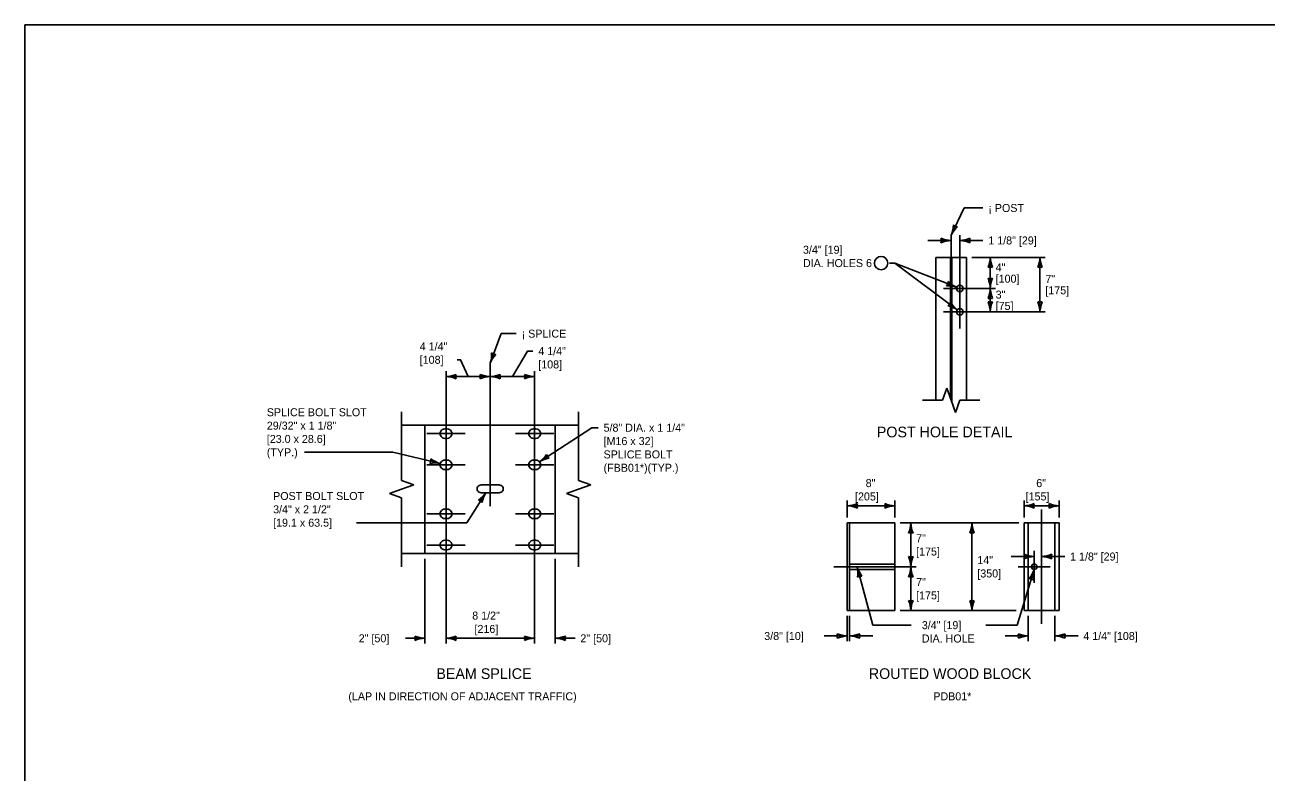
# Model space of a CAD drawing. Extents: x 49991.4 to 50021, y 49987.6 to 50011.4.
# Drawn here: x 49999.38 to 50008.69, y 49993.4 to 49999 of the extents above; entities that cross this region are included whole.
import ezdxf

# ---------------------------------------------------------------- set-up
doc = ezdxf.new("R2010")
doc.units = 0
for name, color, linetype in [('Level 1', 7, 'Continuous'), ('Level 2', 7, 'Continuous'), ('Level 3', 7, 'Continuous'), ('Level 4', 7, 'Continuous'), ('Level 5', 7, 'Continuous'), ('Level 6', 7, 'Continuous')]:
    doc.layers.add(name, color=color, linetype=linetype)

msp = doc.modelspace()

# ---------------------------------------------------------------- linework, layer by layer
at = {"layer": 'Level 1'}
for p, q in [((50006.2125, 49997.2566), (50006.4424, 49997.2566)), ((50006.2125, 49997.2566), (50006.2125, 49996.1857)), ((50006.4424, 49997.2566), (50006.4424, 49996.1857)), ((50002.2084, 49995.9992), (50003.5354, 49995.9992)), ((50002.3835, 49995.0378), (50002.3835, 49995.9992)), ((50002.5326, 49995.9712), (50002.5496, 49995.9712)), ((50003.197, 49995.9712), (50003.214, 49995.9712)), ((50002.5326, 49995.9005), (50002.5496, 49995.9005)), ((50003.197, 49995.9005), (50003.214, 49995.9005)), ((50002.5326, 49995.7373), (50002.5496, 49995.7373)), ((50003.197, 49995.7373), (50003.214, 49995.7373)), ((50002.5326, 49995.6666), (50002.5496, 49995.6666)), ((50003.197, 49995.6666), (50003.214, 49995.6666)), ((50002.9404, 49995.5512), (50002.8037, 49995.5512)), ((50002.8037, 49995.4926), (50002.9404, 49995.4926)), ((50002.5326, 49995.3705), (50002.5496, 49995.3705)), ((50003.197, 49995.3705), (50003.214, 49995.3705)), ((50002.5326, 49995.2997), (50002.5496, 49995.2997)), ((50003.197, 49995.2997), (50003.214, 49995.2997)), ((50005.5486, 49995.2663), (50005.9062, 49995.2663)), ((50005.5486, 49995.2663), (50005.5486, 49994.6097)), ((50005.9062, 49995.2663), (50005.9062, 49994.6097)), ((50006.8742, 49995.2663), (50006.8742, 49994.6097)), ((50006.8742, 49995.2663), (50007.1381, 49995.2663)), ((50006.9065, 49995.2663), (50006.9065, 49994.6097)), ((50007.1058, 49995.2663), (50007.1058, 49994.6097)), ((50007.1381, 49995.2663), (50007.1381, 49994.6097)), ((50002.5326, 49995.1364), (50002.5496, 49995.1364)), ((50003.197, 49995.1364), (50003.214, 49995.1364)), ((50002.2084, 49995.0378), (50003.5354, 49995.0378)), ((50002.5326, 49995.0657), (50002.5496, 49995.0657)), ((50003.197, 49995.0657), (50003.214, 49995.0657)), ((50005.5486, 49994.6097), (50005.9062, 49994.6097)), ((50006.8742, 49994.6097), (50007.1381, 49994.6097))]:
    msp.add_line(p, q, dxfattribs=at)
msp.add_lwpolyline([(49999.3835, 49998.9992), (50016.7501, 49998.9992), (50016.7501, 49987.7988), (49999.3835, 49987.7988)], close=True, dxfattribs=at)
for centre, radius in [((50006.3931, 49997.0236), 0.0237), ((50006.3931, 49996.8482), 0.0237), ((50006.9505, 49994.938), 0.0205)]:
    msp.add_circle(centre, radius, dxfattribs=at)
for centre, major_axis, ratio, start_param, end_param in [((50002.5326, 49995.9359), (-0.0354, 0), 0.998676, 4.712389, 7.853982), ((50002.5496, 49995.9359), (-0.0354, 0), 0.998676, 1.570796, 4.712389), ((50003.197, 49995.9359), (-0.0354, 0), 0.998676, 4.712389, 7.853982), ((50003.214, 49995.9359), (-0.0354, 0), 0.998676, 1.570796, 4.712389), ((50002.5326, 49995.702), (-0.0354, 0), 0.998676, 4.712389, 7.853982), ((50002.5496, 49995.702), (-0.0354, 0), 0.998676, 1.570796, 4.712389), ((50003.197, 49995.702), (-0.0354, 0), 0.998676, 4.712389, 7.853982), ((50003.214, 49995.702), (-0.0354, 0), 0.998676, 1.570796, 4.712389), ((50002.8037, 49995.5219), (-0.0294, 0), 0.995211, 4.712389, 7.853982), ((50002.9404, 49995.5219), (-0.0296, 0), 0.988923, 1.570796, 4.712389), ((50002.5326, 49995.3351), (-0.0354, 0), 0.998676, 4.712389, 7.853982), ((50002.5496, 49995.3351), (-0.0354, 0), 0.998676, 1.570796, 4.712389), ((50003.197, 49995.3351), (-0.0354, 0), 0.998676, 4.712389, 7.853982), ((50003.214, 49995.3351), (-0.0354, 0), 0.998676, 1.570796, 4.712389), ((50002.5326, 49995.1011), (-0.0354, 0), 0.998676, 4.712389, 7.853982), ((50002.5496, 49995.1011), (-0.0354, 0), 0.998676, 1.570796, 4.712389), ((50003.197, 49995.1011), (-0.0354, 0), 0.998676, 4.712389, 7.853982), ((50003.214, 49995.1011), (-0.0354, 0), 0.998676, 1.570796, 4.712389)]:
    msp.add_ellipse(centre, major_axis=major_axis, ratio=ratio, start_param=start_param, end_param=end_param, dxfattribs=at)
at = {"layer": 'Level 2'}
msp.add_circle((50005.8029, 49997.2139), 0.05, dxfattribs=at)
at = {"layer": 'Level 3'}
for p, q in [((50006.3275, 49997.4235), (50006.4252, 49997.6268)), ((50006.4252, 49997.6268), (50006.5665, 49997.6268)), ((50006.3275, 49997.3835), (50006.154, 49997.3835)), ((50006.3931, 49997.3835), (50006.5665, 49997.3835)), ((50005.8667, 49997.2139), (50005.9067, 49997.2139)), ((50005.9067, 49997.2139), (50006.3741, 49996.8625)), ((50005.9067, 49997.2139), (50006.371, 49997.0322)), ((50006.4824, 49997.2566), (50007.034, 49997.2566)), ((50006.6216, 49997.0236), (50006.6216, 49997.2566)), ((50006.994, 49997.2566), (50006.994, 49996.8482)), ((50006.6216, 49996.8482), (50006.6216, 49997.0236)), ((50002.8721, 49996.4632), (50002.955, 49996.6852)), ((50002.955, 49996.6852), (50003.0681, 49996.6852)), ((50002.5411, 49996.3632), (50002.8721, 49996.3632)), ((50003.2055, 49996.3632), (50002.8721, 49996.3632)), ((50003.6342, 49995.9802), (50003.2409, 49995.7249)), ((50003.6822, 49995.9802), (50003.6342, 49995.9802)), ((50002.1431, 49995.796), (50001.4813, 49995.796)), ((50002.4986, 49995.712), (50002.1431, 49995.796)), ((50002.6959, 49995.2684), (50002.8394, 49995.4926)), ((50005.5486, 49995.3063), (50005.5486, 49995.4352)), ((50005.9062, 49995.3952), (50005.5486, 49995.3952)), ((50005.9063, 49995.4352), (50005.9062, 49995.3063)), ((50006.8742, 49995.3063), (50006.8742, 49995.4352)), ((50007.1381, 49995.3952), (50006.8742, 49995.3952)), ((50007.1381, 49995.3063), (50007.1381, 49995.4352)), ((50001.8709, 49995.2684), (50002.6959, 49995.2684)), ((50005.9462, 49995.2663), (50006.8342, 49995.2663)), ((50006.0253, 49994.938), (50006.0253, 49995.2663)), ((50006.4842, 49995.2663), (50006.4842, 49994.6097)), ((50002.3835, 49994.9978), (50002.3835, 49994.3622)), ((50003.3603, 49994.9978), (50003.3603, 49994.3622)), ((50006.7771, 49995.0148), (50006.9505, 49995.0148)), ((50007.0062, 49995.0148), (50007.1796, 49995.0148)), ((50005.7398, 49994.5006), (50005.6225, 49994.938)), ((50006.0253, 49994.938), (50006.0253, 49994.6097)), ((50006.9505, 49994.9175), (50006.823, 49994.5006)), ((50005.9462, 49994.6097), (50006.8144, 49994.6097)), ((50005.5486, 49994.5697), (50005.5486, 49994.3794)), ((50005.5662, 49994.5697), (50005.5662, 49994.3794)), ((50006.9065, 49994.3794), (50006.9065, 49994.5697)), ((50007.1058, 49994.5697), (50007.1058, 49994.3794)), ((50005.5486, 49994.4194), (50005.3752, 49994.4194)), ((50005.7396, 49994.4194), (50005.5662, 49994.4194)), ((50005.7398, 49994.5006), (50006.0281, 49994.5006)), ((50006.5877, 49994.5006), (50006.823, 49994.5006)), ((50006.9065, 49994.4194), (50006.7331, 49994.4194)), ((50007.1058, 49994.4194), (50007.2792, 49994.4194)), ((50002.2377, 49994.4022), (50002.3835, 49994.4022)), ((50002.5411, 49994.4022), (50003.2055, 49994.4022)), ((50003.5085, 49994.4022), (50003.3603, 49994.4022))]:
    msp.add_line(p, q, dxfattribs=at)
for points in [[(50002.7066, 49996.3632), (50002.6505, 49996.4892), (50002.6245, 49996.4892)], [(50003.0388, 49996.3632), (50003.1529, 49996.5544), (50003.1927, 49996.5544)]]:
    msp.add_lwpolyline(points, dxfattribs=at)
for centre, radius, start, end in [((50006.1128, 49997.5141), 0.233, 337.12584, 356.37569), ((50006.3831, 49997.5391), 0.0548, 226.43734, 262.15971), ((50006.3366, 49997.6057), 0.2223, 247.45601, 267.63952), ((50006.1992, 49997.3835), 0.0548, 342.13882, 17.86118), ((50006.5236, 49997.3189), 0.2223, 131.75454, 151.93804), ((50006.3816, 49997.6162), 0.233, 272.82731, 292.07716), ((50006.5213, 49997.3835), 0.0548, 162.13882, 197.86118), ((50006.3389, 49997.1508), 0.233, 92.82731, 112.07716), ((50006.3839, 49997.1614), 0.2223, 67.45601, 87.63952), ((50006.3994, 49997.2657), 0.2223, 337.45601, 357.63952), ((50006.8543, 49997.2681), 0.233, 182.82731, 202.07716), ((50006.7719, 49997.2657), 0.2223, 337.45601, 357.63952), ((50007.2267, 49997.2681), 0.233, 182.82731, 202.07716), ((50006.6216, 49997.1284), 0.0548, 72.13882, 107.86118), ((50006.994, 49997.1284), 0.0548, 72.13882, 107.86118), ((50006.2516, 49997.0789), 0.0548, 320.76761, 356.48997), ((50006.2969, 49996.8113), 0.233, 71.4561, 90.70595), ((50006.4605, 49997.2357), 0.2223, 226.0848, 246.26831), ((50006.6216, 49997.1518), 0.0548, 252.13882, 287.86118), ((50006.3889, 49997.0121), 0.233, 2.82731, 22.07716), ((50006.3994, 49997.0327), 0.2223, 337.45601, 357.63952), ((50006.8437, 49997.0144), 0.2223, 157.45601, 177.63952), ((50006.8543, 49997.0351), 0.233, 182.82731, 202.07716), ((50006.6216, 49996.8954), 0.0548, 72.13882, 107.86118), ((50006.2716, 49996.9395), 0.0548, 305.20124, 340.9236), ((50006.2435, 49996.6696), 0.233, 55.88973, 75.13958), ((50006.5149, 49997.0345), 0.2223, 210.51843, 230.70194), ((50006.6216, 49996.9765), 0.0548, 252.13882, 287.86118), ((50006.3889, 49996.8367), 0.233, 2.82731, 22.07716), ((50006.8437, 49996.8391), 0.2223, 157.45601, 177.63952), ((50006.994, 49996.9765), 0.0548, 252.13882, 287.86118), ((50006.7613, 49996.8367), 0.233, 2.82731, 22.07716), ((50007.2161, 49996.8391), 0.2223, 157.45601, 177.63952), ((50002.6501, 49996.5339), 0.233, 342.34834, 1.59819), ((50003.077, 49996.3769), 0.2223, 136.97704, 157.16055), ((50002.917, 49996.5833), 0.0548, 231.65985, 267.38221), ((50002.5296, 49996.5959), 0.233, 272.82731, 292.07716), ((50002.6693, 49996.3632), 0.0548, 162.13882, 197.86118), ((50002.8813, 49996.5853), 0.2223, 247.45601, 267.63952), ((50002.7439, 49996.3632), 0.0548, 342.13882, 17.86118), ((50002.8606, 49996.5959), 0.233, 272.82731, 292.07716), ((50003.0003, 49996.3632), 0.0548, 162.13882, 197.86118), ((50003.2147, 49996.5853), 0.2223, 247.45601, 267.63952), ((50003.0773, 49996.3632), 0.0548, 342.13882, 17.86118), ((50002.5319, 49996.1411), 0.2223, 67.45601, 87.63952), ((50002.8836, 49996.1305), 0.233, 92.82731, 112.07716), ((50002.8629, 49996.1411), 0.2223, 67.45601, 87.63952), ((50003.217, 49996.1305), 0.233, 92.82731, 112.07716), ((50002.3738, 49995.7415), 0.0548, 328.85016, 4.57253), ((50002.5586, 49995.9261), 0.2223, 234.16736, 254.35086), ((50003.1043, 49995.9136), 0.233, 305.92164, 325.17149), ((50003.3546, 49995.5338), 0.2223, 100.55034, 120.73384), ((50003.3484, 49995.7949), 0.0548, 195.23314, 230.95551), ((50002.4563, 49995.4829), 0.233, 79.53866, 98.78851), ((50002.6573, 49995.6201), 0.2223, 304.8248, 325.00831), ((50003.0416, 49995.3768), 0.233, 150.1961, 169.44595), ((50002.7703, 49995.3846), 0.0548, 39.50761, 75.22997), ((50005.5371, 49995.628), 0.233, 272.82731, 292.07716), ((50005.5395, 49995.1731), 0.2223, 67.45601, 87.63952), ((50005.6768, 49995.3952), 0.0548, 162.13882, 197.86118), ((50005.9154, 49995.6174), 0.2223, 247.45601, 267.63952), ((50005.778, 49995.3952), 0.0548, 342.13882, 17.86118), ((50005.9177, 49995.1625), 0.233, 92.82731, 112.07716), ((50006.8628, 49995.628), 0.233, 272.82731, 292.07716), ((50006.8651, 49995.1731), 0.2223, 67.45601, 87.63952), ((50007.0025, 49995.3952), 0.0548, 162.13882, 197.86118), ((50007.1472, 49995.6174), 0.2223, 247.45601, 267.63952), ((50007.0098, 49995.3952), 0.0548, 342.13882, 17.86118), ((50007.1496, 49995.1625), 0.233, 92.82731, 112.07716), ((50005.8032, 49995.2755), 0.2223, 337.45601, 357.63952), ((50006.258, 49995.2778), 0.233, 182.82731, 202.07716), ((50006.2621, 49995.2755), 0.2223, 337.45601, 357.63952), ((50006.717, 49995.2778), 0.233, 182.82731, 202.07716), ((50006.0253, 49995.1381), 0.0548, 72.13882, 107.86118), ((50006.4842, 49995.1381), 0.0548, 72.13882, 107.86118), ((50006.0253, 49995.0662), 0.0548, 252.13882, 287.86118), ((50005.7926, 49994.9265), 0.233, 2.82731, 22.07716), ((50006.2474, 49994.9288), 0.2223, 157.45601, 177.63952), ((50006.9596, 49995.2369), 0.2223, 247.45601, 267.63952), ((50006.8222, 49995.0148), 0.0548, 342.13882, 17.86118), ((50006.962, 49994.7821), 0.233, 92.82731, 112.07716), ((50006.9947, 49995.2475), 0.233, 272.82731, 292.07716), ((50006.997, 49994.7927), 0.2223, 67.45601, 87.63952), ((50007.1344, 49995.0148), 0.0548, 162.13882, 197.86118), ((50005.4056, 49994.8893), 0.2223, 352.45601, 12.63952), ((50005.8444, 49995.0093), 0.233, 197.82731, 217.07716), ((50005.8032, 49994.9471), 0.2223, 337.45601, 357.63952), ((50006.258, 49994.9495), 0.233, 182.82731, 202.07716), ((50006.7395, 49994.9877), 0.2223, 321.4053, 341.58881), ((50007.1773, 49994.8642), 0.233, 166.7766, 186.02645), ((50005.6557, 49994.8141), 0.0548, 87.13882, 122.86118), ((50006.0253, 49994.8098), 0.0548, 72.13882, 107.86118), ((50006.915, 49994.7943), 0.0548, 56.08811, 91.81047), ((50006.0253, 49994.7379), 0.0548, 252.13882, 287.86118), ((50005.7926, 49994.5982), 0.233, 2.82731, 22.07716), ((50006.2474, 49994.6005), 0.2223, 157.45601, 177.63952), ((50006.4842, 49994.7379), 0.0548, 252.13882, 287.86118), ((50006.2515, 49994.5982), 0.233, 2.82731, 22.07716), ((50006.7064, 49994.6005), 0.2223, 157.45601, 177.63952), ((50002.3927, 49994.6243), 0.2223, 247.45601, 267.63952), ((50002.2553, 49994.4022), 0.0548, 342.13882, 17.86118), ((50002.5296, 49994.6349), 0.233, 272.82731, 292.07716), ((50002.6693, 49994.4022), 0.0548, 162.13882, 197.86118), ((50003.2147, 49994.6243), 0.2223, 247.45601, 267.63952), ((50003.0773, 49994.4022), 0.0548, 342.13882, 17.86118), ((50003.3488, 49994.6349), 0.233, 272.82731, 292.07716), ((50003.4885, 49994.4022), 0.0548, 162.13882, 197.86118), ((50005.5578, 49994.6415), 0.2223, 247.45601, 267.63952), ((50005.4204, 49994.4194), 0.0548, 342.13882, 17.86118), ((50005.5601, 49994.1867), 0.233, 92.82731, 112.07716), ((50005.5547, 49994.6521), 0.233, 272.82731, 292.07716), ((50005.557, 49994.1973), 0.2223, 67.45601, 87.63952), ((50005.6944, 49994.4194), 0.0548, 162.13882, 197.86118), ((50006.9156, 49994.6415), 0.2223, 247.45601, 267.63952), ((50006.7783, 49994.4194), 0.0548, 342.13882, 17.86118), ((50006.918, 49994.1867), 0.233, 92.82731, 112.07716), ((50007.0943, 49994.6521), 0.233, 272.82731, 292.07716), ((50007.0967, 49994.1973), 0.2223, 67.45601, 87.63952), ((50007.234, 49994.4194), 0.0548, 162.13882, 197.86118), ((50002.395, 49994.1695), 0.233, 92.82731, 112.07716), ((50002.5319, 49994.1801), 0.2223, 67.45601, 87.63952), ((50003.217, 49994.1695), 0.233, 92.82731, 112.07716), ((50003.3511, 49994.1801), 0.2223, 67.45601, 87.63952)]:
    msp.add_arc(centre, radius, start, end, dxfattribs=at)
at = {"layer": 'Level 4'}
for p, q in [((50006.322, 49997.2566), (50006.322, 49996.201)), ((50006.3329, 49997.2566), (50006.3329, 49996.1701)), ((50003.3603, 49995.0378), (50003.3603, 49995.9992)), ((50005.5662, 49995.2663), (50005.5662, 49994.6097)), ((50005.5662, 49994.9585), (50005.9062, 49994.9585)), ((50005.5662, 49994.9175), (50005.9062, 49994.9175))]:
    msp.add_line(p, q, dxfattribs=at)
at = {"layer": 'Level 5'}
for p, q in [((50006.3275, 49997.2566), (50006.3275, 49997.4235)), ((50006.3931, 49997.4235), (50006.3931, 49996.7245)), ((50006.2694, 49997.0236), (50006.6616, 49997.0236)), ((50006.2694, 49996.8482), (50007.034, 49996.8482)), ((50002.5411, 49994.3622), (50002.5411, 49996.4032)), ((50002.8721, 49995.3926), (50002.8721, 49996.4632)), ((50003.2055, 49994.3622), (50003.2055, 49996.4032)), ((50002.6851, 49995.9359), (50002.3971, 49995.9359)), ((50003.3495, 49995.9359), (50003.0615, 49995.9359)), ((50002.6851, 49995.702), (50002.3971, 49995.702)), ((50003.3495, 49995.702), (50003.0615, 49995.702)), ((50007.0062, 49995.3663), (50007.0062, 49994.5097)), ((50002.6851, 49995.3351), (50002.3971, 49995.3351)), ((50003.3495, 49995.3351), (50003.0615, 49995.3351)), ((50002.6851, 49995.1011), (50002.3971, 49995.1011)), ((50003.3495, 49995.1011), (50003.0615, 49995.1011)), ((50006.9505, 49994.8175), (50006.9505, 49995.0585)), ((50005.4486, 49994.938), (50006.0653, 49994.938)), ((50006.8299, 49994.938), (50007.071, 49994.938))]:
    msp.add_line(p, q, dxfattribs=at)
at = {"layer": 'Level 6'}
for p, q in [((50006.1125, 49996.1857), (50006.2626, 49996.1857)), ((50006.2626, 49996.1857), (50006.295, 49996.2771)), ((50006.3274, 49996.1857), (50006.295, 49996.2771)), ((50006.3598, 49996.0943), (50006.3274, 49996.1857)), ((50006.3598, 49996.0943), (50006.3922, 49996.1857)), ((50006.3922, 49996.1857), (50006.5424, 49996.1857)), ((50002.2084, 49996.0992), (50002.2084, 49995.5834)), ((50003.5354, 49996.0992), (50003.5354, 49995.5834)), ((50002.2998, 49995.551), (50002.2084, 49995.5834)), ((50002.2998, 49995.551), (50002.2084, 49995.5186)), ((50003.6268, 49995.551), (50003.5354, 49995.5834)), ((50003.6268, 49995.551), (50003.5354, 49995.5186)), ((50002.2084, 49995.5186), (50002.117, 49995.4862)), ((50002.2084, 49995.4538), (50002.117, 49995.4862)), ((50002.2084, 49995.4538), (50002.2084, 49994.9378)), ((50003.5354, 49995.5186), (50003.444, 49995.4862)), ((50003.5354, 49995.4538), (50003.444, 49995.4862)), ((50003.5354, 49995.4538), (50003.5354, 49994.9378))]:
    msp.add_line(p, q, dxfattribs=at)

# ---------------------------------------------------------------- texts
at = {"layer": 'Level 2'}
for s, height, p in [('¡ POST', 0.06, (50006.6065, 49997.5968)), ('1 1/8" [29]', 0.06, (50006.6065, 49997.3535)), ('4"', 0.06, (50006.6616, 49997.152)), ('[100]', 0.06, (50006.6616, 49997.067)), ('7"', 0.06, (50007.034, 49997.0649)), ('[175]', 0.06, (50007.034, 49996.9799)), ('3"', 0.06, (50006.6616, 49996.9478)), ('[75]', 0.06, (50006.6616, 49996.8628)), ('¡ SPLICE', 0.06, (50003.1081, 49996.6552)), ('4 1/4"', 0.06, (50003.2327, 49996.5244)), ('[108]', 0.06, (50003.2327, 49996.4244)), ('5/8" DIA. x 1 1/4"', 0.06, (50003.7222, 49995.9502)), ('[M16 x 32]', 0.06, (50003.7222, 49995.8502)), ('POST HOLE DETAIL', 0.08, (50005.7707, 49995.9082)), ('SPLICE BOLT ', 0.06, (50003.7222, 49995.7502)), ('(FBB01*)(TYP.) ', 0.06, (50003.7222, 49995.6502)), ('8"', 0.06, (50005.6871, 49995.5352)), ('6"', 0.06, (50006.9658, 49995.5352)), ('[205]', 0.06, (50005.6072, 49995.4352)), ('[155]', 0.06, (50006.8859, 49995.4352)), ('7"', 0.06, (50006.0653, 49995.1224)), ('[175]', 0.06, (50006.0653, 49995.0224)), ('14"', 0.06, (50006.5242, 49994.958)), ('1 1/8" [29]', 0.06, (50007.2196, 49994.9848)), ('[350]', 0.06, (50006.5242, 49994.858)), ('7"', 0.06, (50006.0653, 49994.7938)), ('[175]', 0.06, (50006.0653, 49994.6938)), ('8 1/2"', 0.06, (50002.7376, 49994.5422)), ('2" [50]', 0.06, (50001.8866, 49994.3722)), ('[216]', 0.06, (50002.7545, 49994.4422)), ('2" [50]', 0.06, (50003.5485, 49994.3722)), ('3/8" [10]', 0.06, (50004.9266, 49994.3894)), ('4 1/4" [108]', 0.06, (50007.3192, 49994.3894)), ('BEAM SPLICE', 0.08, (50002.4688, 49994.0974)), ('ROUTED WOOD BLOCK', 0.08, (50005.7107, 49994.0974)), ('(LAP IN DIRECTION OF ADJACENT TRAFFIC)', 0.06, (50001.8089, 49993.9374)), ('PDB01*', 0.06, (50006.1941, 49993.9374))]:
    msp.add_text(s, height=height, dxfattribs=at).set_placement(p)
for s, p in [('3/4" [19]', (50005.2171, 49997.2839)), ('DIA. HOLES 6', (50005.2171, 49997.1839)), ('4 1/4"', (50002.344, 49996.5592)), ('[108]', (50002.344, 49996.4592)), ('SPLICE BOLT SLOT', (50001.1976, 49996.066)), ('29/32" x 1 1/8"', (50001.1976, 49995.966)), ('[23.0 x 28.6]', (50001.1976, 49995.866)), ('(TYP.)', (50001.1976, 49995.766)), ('POST BOLT SLOT', (50001.2448, 49995.4384)), ('3/4" x 2 1/2"', (50001.2448, 49995.3384)), ('[19.1 x 63.5]', (50001.2448, 49995.2384)), ('3/4" [19]', (50006.1081, 49994.4706)), ('DIA. HOLE', (50006.1081, 49994.3706))]:
    msp.add_text(s, height=0.06, rotation=360, dxfattribs=at).set_placement(p)

doc.saveas('drawing.dxf')
